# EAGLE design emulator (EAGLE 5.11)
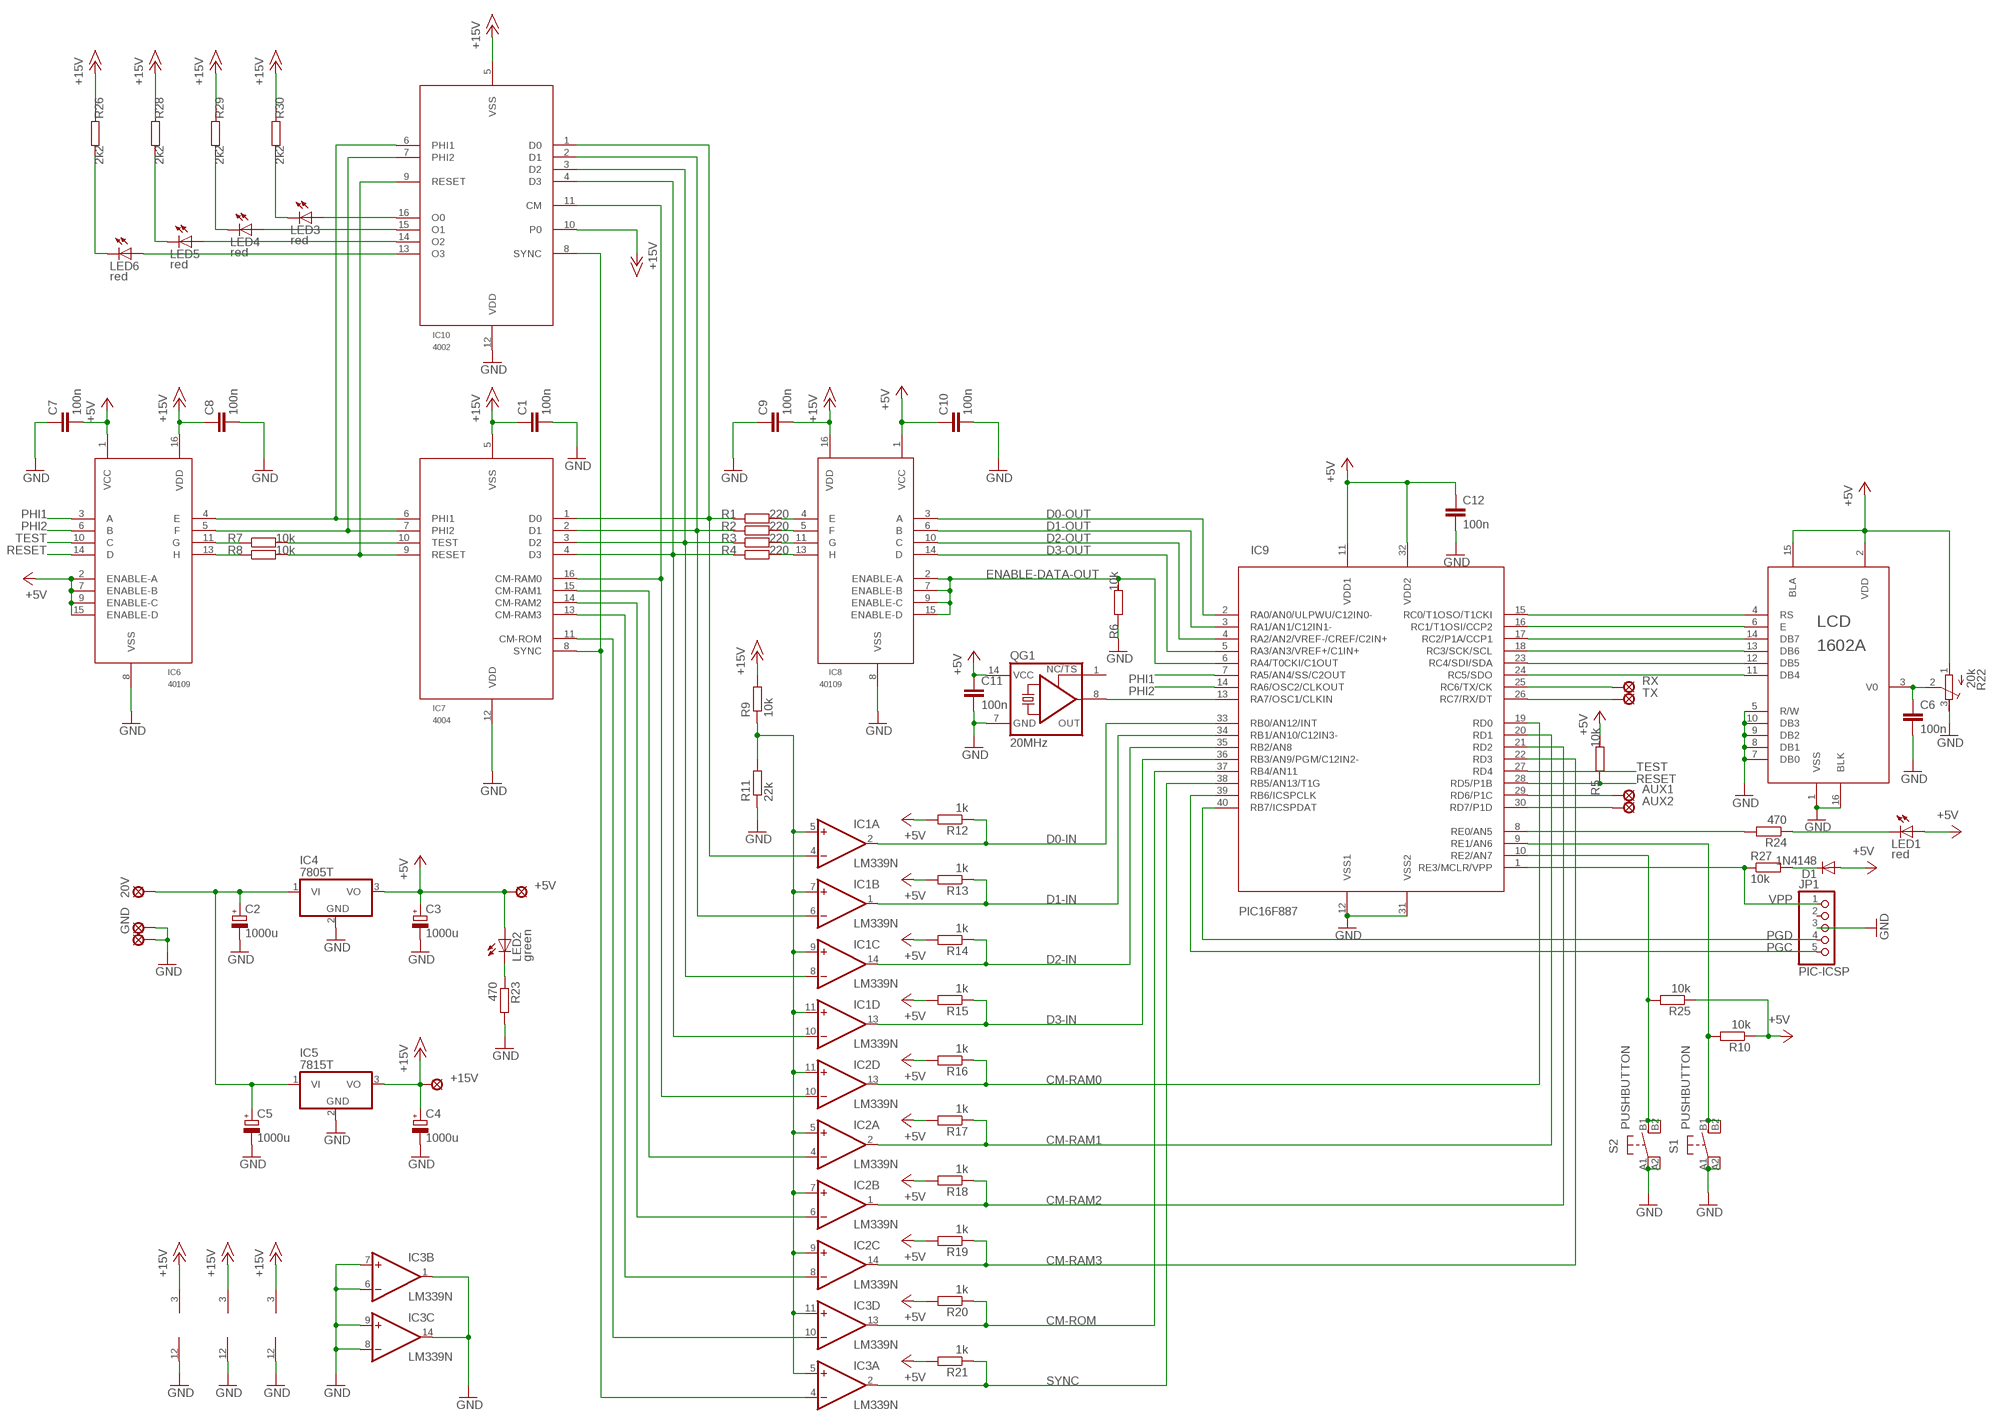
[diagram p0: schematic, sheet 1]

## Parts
20V  LSP10  [LSP10]
+5V  LSP10  [LSP10]
+15V  LSP10  [LSP10]
AUX1  LSP10  [LSP10]
AUX2  LSP10  [LSP10]
C1  100n  C-EU050-050X075  [C050-050X075]
C2  1000u  CPOL-EUE7.5-16  [E7,5-16]
C3  1000u  CPOL-EUE7.5-16  [E7,5-16]
C4  1000u  CPOL-EUE7.5-16  [E7,5-16]
C5  1000u  CPOL-EUE7.5-16  [E7,5-16]
C6  100n  C-EU050-050X075  [C050-050X075]
C7  100n  C-EU050-050X075  [C050-050X075]
C8  100n  C-EU050-050X075  [C050-050X075]
C9  100n  C-EU050-050X075  [C050-050X075]
C10  100n  C-EU050-050X075  [C050-050X075]
C11  100n  C-EU050-055X075  [C050-055X075]
C12  100n  C-EU050-050X075  [C050-050X075]
D1  1N4148  1N4148DO35-7  [DO35-7]
GND  LSP10  [LSP10]
GND29  LSP10  [LSP10]
IC1  LM339N  [DIL14]
IC2  LM339N  [DIL14]
IC3  LM339N  [DIL14]
IC4  7805T  [TO220H]
IC5  7815T  [TO220H]
IC6  40109  [DIL16]
IC7  4004  [DIL16/DIL40]
IC8  40109  [DIL16]
IC9  PIC16F887  [DIL40]
IC10  4002  [DIL16]
JP1  PIC-ICSP  PINHD-1X5  [1X05]
LCD  1602A  [1602A]
LED1  red  LED5MM  [LED5MM]
LED2  green  LED5MM  [LED5MM]
LED3  red  LED5MM  [LED5MM]
LED4  red  LED5MM  [LED5MM]
LED5  red  LED5MM  [LED5MM]
LED6  red  LED5MM  [LED5MM]
QG1  20MHz  XO-14  [DIL14S]
R1  220  R-EU_0309/10  [0309/10]
R2  220  R-EU_0309/10  [0309/10]
R3  220  R-EU_0309/10  [0309/10]
R4  220  R-EU_0309/10  [0309/10]
R5  10k  R-EU_0309/10  [0309/10]
R6  10k  R-EU_0309/10  [0309/10]
R7  10k  R-EU_0309/10  [0309/10]
R8  10k  R-EU_0309/10  [0309/10]
R9  10k  R-EU_0309/10  [0309/10]
R10  10k  R-EU_0309/10  [0309/10]
R11  22k  R-EU_0309/10  [0309/10]
R12  1k  R-EU_0309/10  [0309/10]
R13  1k  R-EU_0309/10  [0309/10]
R14  1k  R-EU_0309/10  [0309/10]
R15  1k  R-EU_0309/10  [0309/10]
R16  1k  R-EU_0309/10  [0309/10]
R17  1k  R-EU_0309/10  [0309/10]
R18  1k  R-EU_0309/10  [0309/10]
R19  1k  R-EU_0309/10  [0309/10]
R20  1k  R-EU_0309/10  [0309/10]
R21  1k  R-EU_0309/10  [0309/10]
R22  20k  R-TRIMM3339P  [RTRIM3339P]
R23  470  R-EU_0309/10  [0309/10]
R24  470  R-EU_0309/10  [0309/10]
R25  10k  R-EU_0309/10  [0309/10]
R26  2k2  R-EU_0309/10  [0309/10]
R27  10k  R-EU_0309/10  [0309/10]
R28  2k2  R-EU_0309/10  [0309/10]
R29  2k2  R-EU_0309/10  [0309/10]
R30  2k2  R-EU_0309/10  [0309/10]
RX  LSP10  [LSP10]
S1  PUSHBUTTON  [PUSHBUTTON]
S2  PUSHBUTTON  [PUSHBUTTON]
TX  LSP10  [LSP10]

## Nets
+5V: +5V.MP C3.+ C7.2 C10.1 C11.1 C12.1 D1.A IC4.3(VO) IC6.1(VCC) IC6.2(ENABLE-A) IC6.7(ENABLE-B) IC6.9(ENABLE-C) IC6.15(ENABLE-D) IC8.1(VCC) IC9.11(VDD1) IC9.32(VDD2) LCD.2(VDD) LCD.15(BLA) LED1.A LED2.A QG1.14(VCC) R5.2 R10.1 R12.2 R13.2 R14.2 R15.2 R16.2 R17.2 R18.2 R19.2 R20.2 R21.2 R22.1(E) R25.1
+15V: +15V.MP C1.1 C4.+ C8.1 C9.2 IC1.3(P:V+) IC2.3(P:V+) IC3.3(P:V+) IC5.3(VO) IC6.16(VDD) IC7.5(VSS) IC8.16(VDD) IC10.5(VSS) IC10.10(P0) R9.2 R26.1 R28.1 R29.1 R30.1
CM-RAM0: IC2.13(D:OUT) IC9.19(RD0) R16.1
CM-RAM1: IC2.2(A:OUT) IC9.20(RD1) R17.1
CM-RAM2: IC2.1(B:OUT) IC9.21(RD2) R18.1
CM-RAM3: IC2.14(C:OUT) IC9.22(RD3) R19.1
CM-ROM: IC3.13(D:OUT) IC9.37(RB4/AN11) R20.1
D0-IN: IC1.2(A:OUT) IC9.33(RB0/AN12/INT) R12.1
D0-OUT: IC8.3(A) IC9.2(RA0/AN0/ULPWU/C12IN0-)
D1-IN: IC1.1(B:OUT) IC9.34(RB1/AN10/C12IN3-) R13.1
D1-OUT: IC8.6(B) IC9.3(RA1/AN1/C12IN1-)
D2-IN: IC1.14(C:OUT) IC9.35(RB2/AN8) R14.1
D2-OUT: IC8.10(C) IC9.4(RA2/AN2/VREF-/CREF/C2IN+)
D3-IN: IC1.13(D:OUT) IC9.36(RB3/AN9/PGM/C12IN2-) R15.1
D3-OUT: IC8.14(D) IC9.5(RA3/AN3/VREF+/C1IN+)
ENABLE-DATA-OUT: IC8.2(ENABLE-A) IC8.7(ENABLE-B) IC8.9(ENABLE-C) IC8.15(ENABLE-D) IC9.6(RA4/T0CKI/C1OUT) R6.2
GND: C1.2 C2.- C3.- C4.- C5.- C6.2 C7.1 C8.2 C9.1 C10.2 C11.2 C12.2 GND29.MP GND.MP IC1.12(P:GND) IC2.12(P:GND) IC3.1(B:OUT) IC3.6(B:-IN) IC3.7(B:+IN) IC3.8(C:-IN) IC3.9(C:+IN) IC3.12(P:GND) IC3.14(C:OUT) IC4.2(GND) IC5.2(GND) IC6.8(VSS) IC7.12(VDD) IC8.8(VSS) IC9.12(VSS1) IC9.31(VSS2) IC10.12(VDD) JP1.3 LCD.1(VSS) LCD.5(R/W) LCD.7(DB0) LCD.8(DB1) LCD.9(DB2) LCD.10(DB3) LCD.16(BLK) QG1.7(GND) R6.1 R11.1 R22.3(A) R23.2 S1.A1(P) S1.A2(P1) S2.A1(P) S2.A2(P1)
LCD-DB4: IC9.24(RC5/SDO) LCD.11(DB4)
LCD-DB5: IC9.23(RC4/SDI/SDA) LCD.12(DB5)
LCD-DB6: IC9.18(RC3/SCK/SCL) LCD.13(DB6)
LCD-DB7: IC9.17(RC2/P1A/CCP1) LCD.14(DB7)
LCD-E: IC9.16(RC1/T1OSI/CCP2) LCD.6(E)
LCD-RS: IC9.15(RC0/T1OSO/T1CKI) LCD.4(RS)
N$1: IC1.4(A:-IN) IC7.1(D0) IC10.1(D0) R1.1
N$2: IC1.6(B:-IN) IC7.2(D1) IC10.2(D1) R2.1
N$3: IC1.8(C:-IN) IC7.3(D2) IC10.3(D2) R3.1
N$4: IC1.10(D:-IN) IC7.4(D3) IC10.4(D3) R4.1
N$5: IC8.4(E) R1.2
N$6: IC8.5(F) R2.2
N$7: IC8.11(G) R3.2
N$8: IC8.13(H) R4.2
N$9: IC6.4(E) IC7.6(PHI1) IC10.6(PHI1)
N$10: IC6.5(F) IC7.7(PHI2) IC10.7(PHI2)
N$11: IC6.11(G) R7.1
N$12: IC6.13(H) R8.1
N$15: IC7.10(TEST) R7.2
N$16: IC7.9(RESET) IC10.9(RESET) R8.2
N$17: IC1.5(A:+IN) IC1.7(B:+IN) IC1.9(C:+IN) IC1.11(D:+IN) IC2.5(A:+IN) IC2.7(B:+IN) IC2.9(C:+IN) IC2.11(D:+IN) IC3.5(A:+IN) IC3.11(D:+IN) R9.1 R11.2
N$19: IC2.10(D:-IN) IC7.16(CM-RAM0) IC10.11(CM)
N$20: IC2.4(A:-IN) IC7.15(CM-RAM1)
N$21: IC2.6(B:-IN) IC7.14(CM-RAM2)
N$22: IC2.8(C:-IN) IC7.13(CM-RAM3)
N$23: IC3.10(D:-IN) IC7.11(CM-ROM)
N$24: IC3.4(A:-IN) IC7.8(SYNC) IC10.8(SYNC)
N$25: C6.1 LCD.3(V0) R22.2(S)
N$26: IC9.13(RA7/OSC1/CLKIN) QG1.8(OUT)
N$27: LED1.K(C) R24.1
N$28: 20V.MP C2.+ C5.+ IC4.1(VI) IC5.1(VI)
N$29: AUX1.MP IC9.29(RD6/P1C)
N$30: AUX2.MP IC9.30(RD7/P1D)
N$31: D1.C R27.2
N$32: IC9.9(RE1/AN6) R10.2 S1.B1(S) S1.B2(S1)
N$33: IC9.10(RE2/AN7) R25.2 S2.B1(S) S2.B2(S1)
N$34: LED2.K(C) R23.1
N$40: IC9.25(RC6/TX/CK) RX.MP
N$41: IC9.26(RC7/RX/DT) TX.MP
N$42: IC9.8(RE0/AN5) R24.2
N$47: IC10.16(O0) LED3.A
N$48: IC10.15(O1) LED4.A
N$49: IC10.14(O2) LED5.A
N$50: IC10.13(O3) LED6.A
N$51: LED3.K(C) R30.2
N$52: LED4.K(C) R29.2
N$53: LED5.K(C) R28.2
N$54: LED6.K(C) R26.2
PGC: IC9.39(RB6/ICSPCLK) JP1.5
PGD: IC9.40(RB7/ICSPDAT) JP1.4
PHI1: IC6.3(A) IC9.7(RA5/AN4/SS/C2OUT)
PHI2: IC6.6(B) IC9.14(RA6/OSC2/CLKOUT)
RESET: IC6.14(D) IC9.28(RD5/P1B) R5.1
SYNC: IC3.2(A:OUT) IC9.38(RB5/AN13/T1G) R21.1
TEST: IC6.10(C) IC9.27(RD4)
VPP: IC9.1(RE3/MCLR/VPP) JP1.1 R27.1
Unconnected: JP1.2 QG1.1(TS)

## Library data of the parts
20V +5V +15V AUX1 AUX2 GND GND29 RX TX = solpad:LSP10: SOLDER PAD
C1 C6-C12 = rcl:C-EU: CAPACITOR, European symbol
C2-C5 = rcl:CPOL-EU: POLARIZED CAPACITOR, European symbol
D1 = diode:1N4148: DIODE
IC1-IC3 = linear:LM339: Low Power Low Offset Voltage Quad Comparators with open collector; LM139/LM239/LM339/LM2901/LM3302
IC4 IC5 = linear:78*: Positive VOLTAGE REGULATOR Source: http://cache.national.com/ds/LM/LM78L05.pdf http://www.fairchildsemi.com/ds/LM/LM7805.pdf
IC6 IC8 = 4004:40109
IC7 = 4004:4004
IC9 = pic16f887:PIC16F887
IC10 = 4004:4002
JP1 = pinhead:PINHD-1X5: PIN HEADER
LCD = 1602A:1602A
LED1-LED6 = led:LED: LED
QG1 = crystal:XO-: CRYSTAL; OC_FARNELL: unknown; OC_NEWARK: unknown
R1-R21 R23-R30 = rcl:R-EU_: RESISTOR, European symbol
R22 = rcl:R-TRIMM: Trimm resistor
S1 S2 = cartridge:PUSHBUTTON

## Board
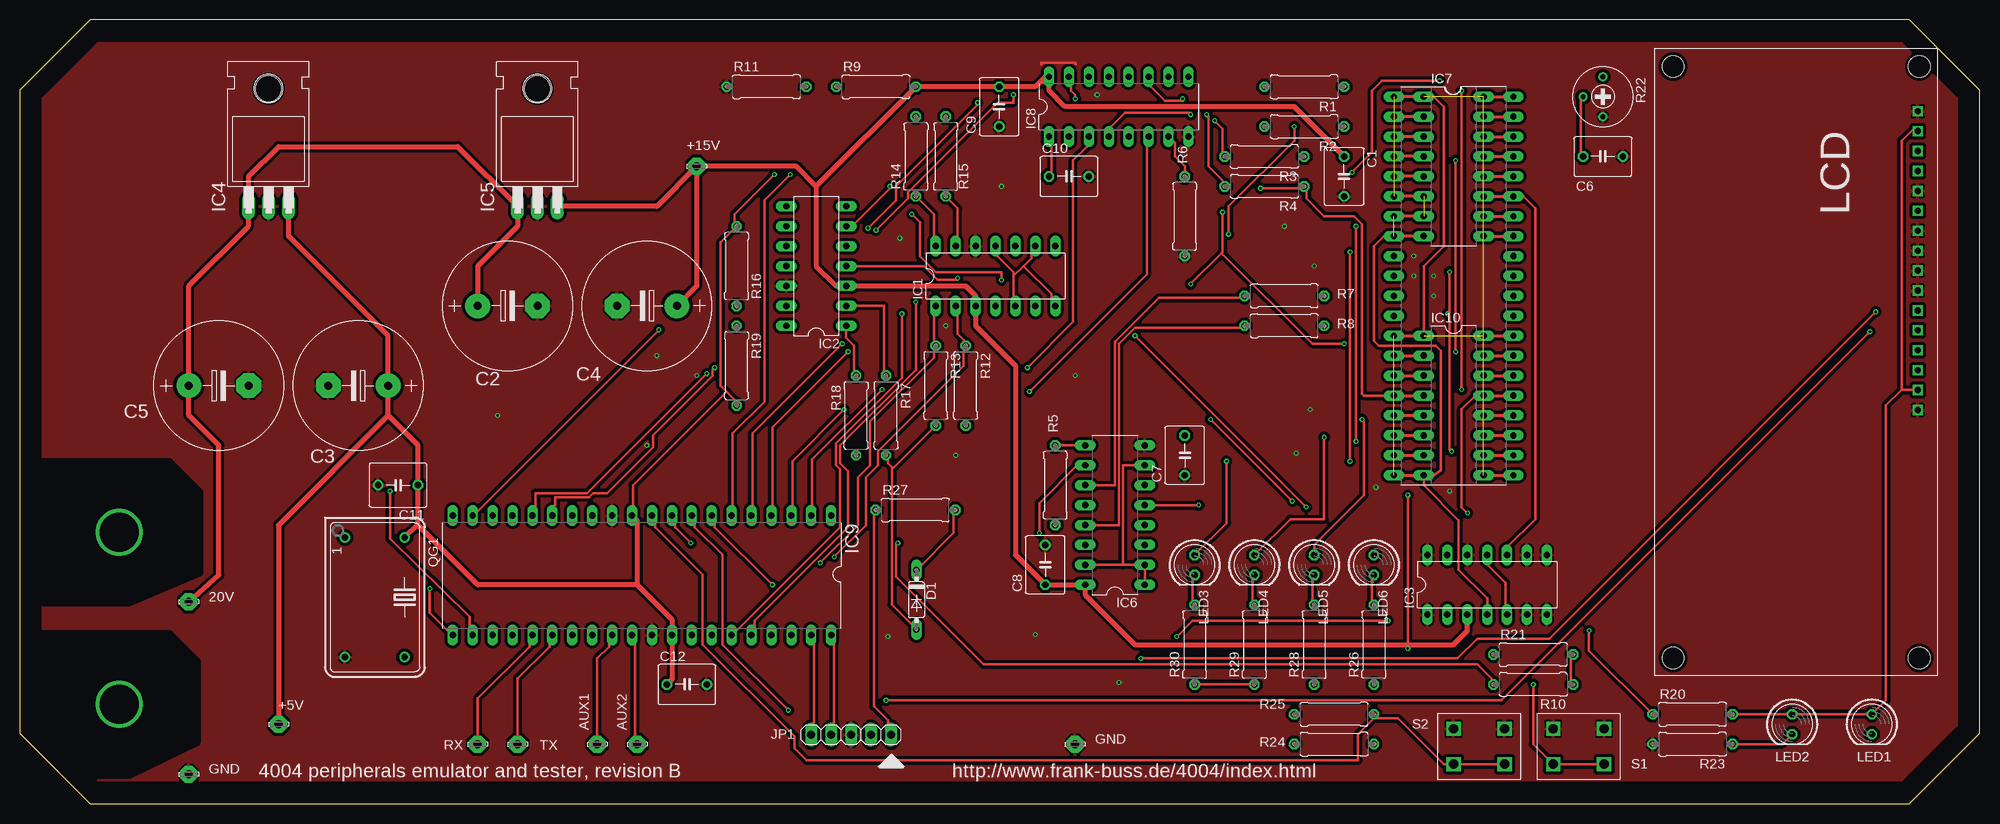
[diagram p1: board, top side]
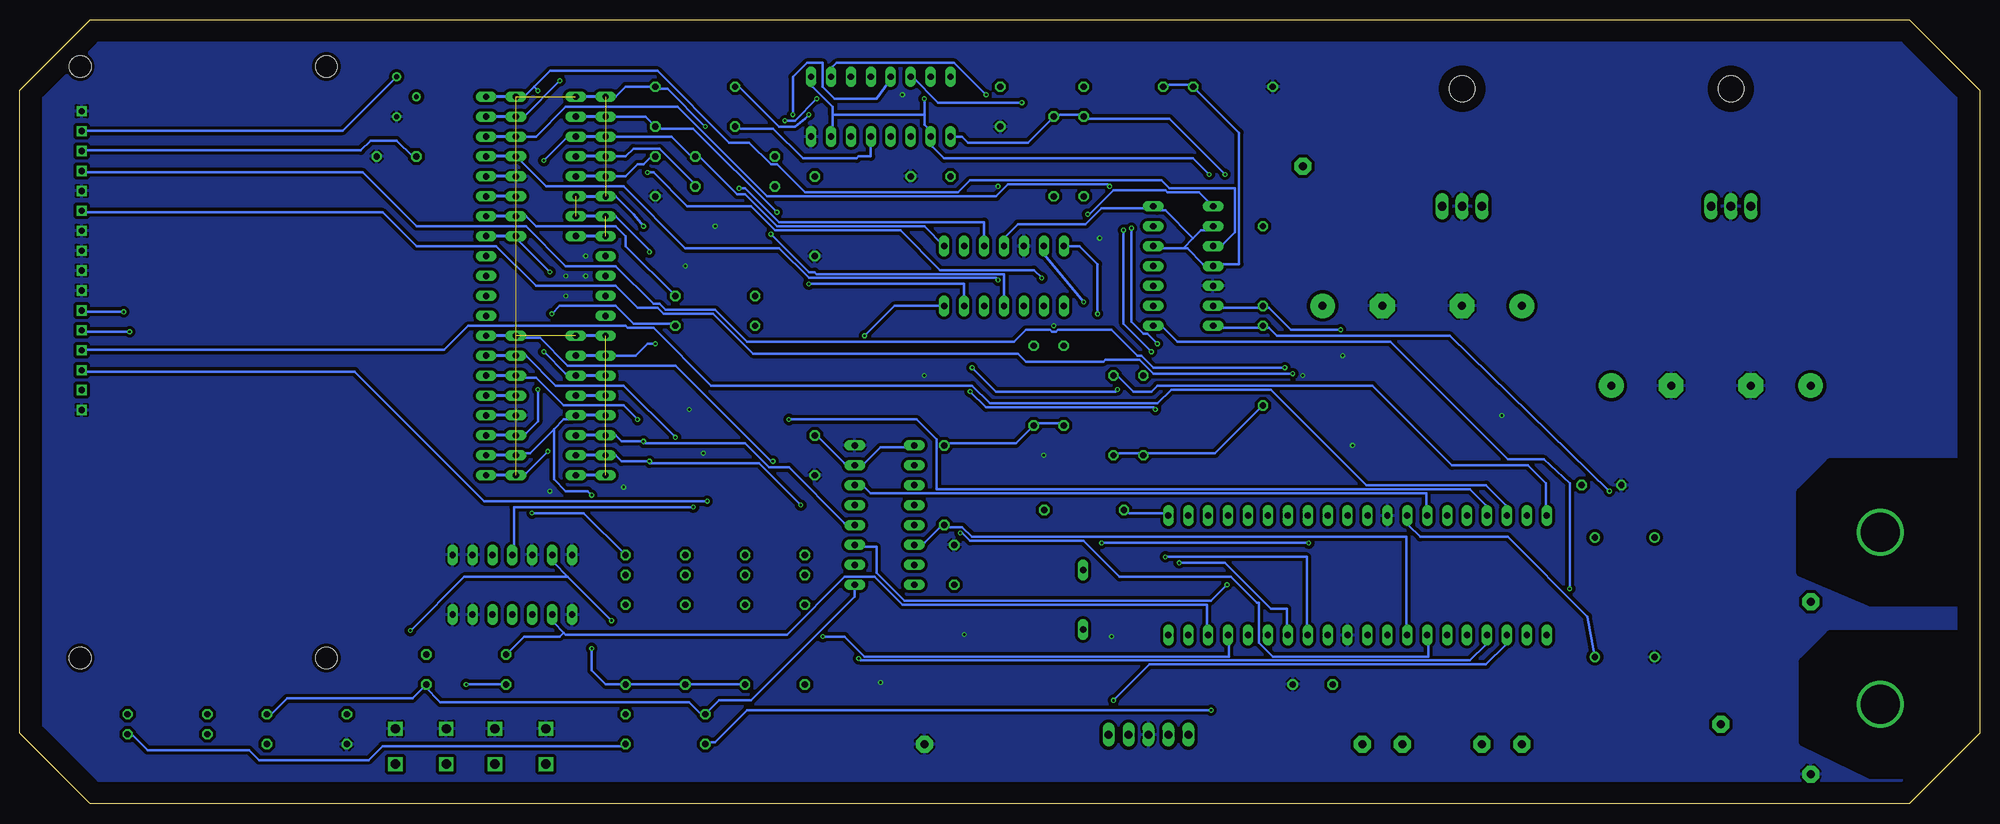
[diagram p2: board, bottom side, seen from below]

Size 250 x 100 mm. Coordinates in mm from the lower left corner, seen from the top.
Outline: 9,0 241,0 250,9 250,91 241,100 9,100 0,91 0,9 9,0
Copper layers (1*16): Top 0.035mm / dielectric 1.5mm / Bottom 0.035mm
Design rules "ITead_rule *": minimum track width 12mil, minimum drill 12mil, track to track 8mil, track to pad 8mil, pad to pad 8mil, via to via 8mil, smd to smd 0mil, copper to edge 10mil, drill to drill 10mil, minimum pad ring 10mil, minimum via ring 6mil, stop-mask expansion 2mil, vias tented up to drill 100mil, thermal gap 10mil
tRestrict: area 2.5,3.8 to 22.5,21.6; area 2.5,25.8 to 22.9,43.5
bRestrict: area 2.5,3.8 to 22.5,21.6; area 2.5,25.8 to 22.9,43.5

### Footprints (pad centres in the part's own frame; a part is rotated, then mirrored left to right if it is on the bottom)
LSP10 = drill 1.016 pad 2.159 octagon: MP 0,0
C050-050X075 = drill 0.813 octagon: 1 -2.54,0; 2 2.54,0
E7,5-16 = drill 1.016 pad 3.15 round: + -3.81,0 | drill 1.016 pad 3.15 octagon: - 3.81,0
C050-055X075 = drill 0.813 octagon: 1 -2.54,0; 2 2.54,0
DO35-7 = drill 0.813 long: A 3.81,0; C -3.81,0
DIL14 = drill 0.813 long: 1 -7.62,-3.81; 2 -5.08,-3.81; 3 -2.54,-3.81; 4 0,-3.81; 5 2.54,-3.81; 6 5.08,-3.81; 7 7.62,-3.81; 8 7.62,3.81; 9 5.08,3.81; 10 2.54,3.81; 11 0,3.81; 12 -2.54,3.81; 13 -5.08,3.81; 14 -7.62,3.81
TO220H = drill 1.118 long: 1 -2.54,-10.16; 2 0,-10.16; 3 2.54,-10.16 | hole 3.302: 0,4.826
DIL16 = drill 0.813 long: 1 -7.62,-3.81; 2 -5.08,-3.81; 3 -2.54,-3.81; 4 0,-3.81; 5 2.54,-3.81; 6 5.08,-3.81; 7 7.62,-3.81; 8 10.16,-3.81; 9 10.16,3.81; 10 7.62,3.81; 11 5.08,3.81; 12 2.54,3.81; 13 0,3.81; 14 -2.54,3.81; 15 -5.08,3.81; 16 -7.62,3.81
DIL16/DIL40 = drill 0.813 long: 1 -8.89,-3.81; 2 -6.35,-3.81; 3 -3.81,-3.81; 4 -1.27,-3.81; 5 1.27,-3.81; 6 3.81,-3.81; 7 6.35,-3.81; 8 8.89,-3.81; 9 8.89,3.81; 10 6.35,3.81; 11 3.81,3.81; 12 1.27,3.81; 13 -1.27,3.81; 14 -3.81,3.81; 15 -6.35,3.81; 16 -8.89,3.81; 17 -8.89,-7.62; 18 -6.35,-7.62; 19 6.35,-7.62; 20 8.89,-7.62; 21 -3.81,-7.62; 22 -1.27,-7.62; 23 3.81,-7.62; 24 1.27,-7.62; 25 11.43,-7.62; 26 13.97,-7.62; 27 16.51,-7.62; 28 19.05,-7.62; 29 21.59,-7.62; 30 24.13,-7.62; 31 26.67,-7.62; 32 29.21,-7.62; 33 31.75,-7.62; 34 34.29,-7.62; 35 36.83,-7.62; 36 39.37,-7.62; 37 39.37,7.62; 38 36.83,7.62; 39 34.29,7.62; 40 31.75,7.62; 41 29.21,7.62; 42 26.67,7.62; 43 24.13,7.62; 44 21.59,7.62; 45 19.05,7.62; 46 16.51,7.62; 47 13.97,7.62; 48 11.43,7.62; 49 8.89,7.62; 50 6.35,7.62; 51 3.81,7.62; 52 1.27,7.62; 53 -1.27,7.62; 54 -3.81,7.62; 55 -6.35,7.62; 56 -8.89,7.62
DIL40 = drill 0.813 long: 1 -24.13,-7.62; 2 -21.59,-7.62; 3 -19.05,-7.62; 4 -16.51,-7.62; 5 -13.97,-7.62; 6 -11.43,-7.62; 7 -8.89,-7.62; 8 -6.35,-7.62; 9 -3.81,-7.62; 10 -1.27,-7.62; 11 1.27,-7.62; 12 3.81,-7.62; 13 6.35,-7.62; 14 8.89,-7.62; 15 11.43,-7.62; 16 13.97,-7.62; 17 16.51,-7.62; 18 19.05,-7.62; 19 21.59,-7.62; 20 24.13,-7.62; 21 24.13,7.62; 22 21.59,7.62; 23 19.05,7.62; 24 16.51,7.62; 25 13.97,7.62; 26 11.43,7.62; 27 8.89,7.62; 28 6.35,7.62; 29 3.81,7.62; 30 1.27,7.62; 31 -1.27,7.62; 32 -3.81,7.62; 33 -6.35,7.62; 34 -8.89,7.62; 35 -11.43,7.62; 36 -13.97,7.62; 37 -16.51,7.62; 38 -19.05,7.62; 39 -21.59,7.62; 40 -24.13,7.62
1X05 = drill 1.016 long: 1 -5.08,0; 2 -2.54,0; 3 0,0; 4 2.54,0; 5 5.08,0
1602A = drill 0.8 square: 1 -31.15,14.29; 2 -28.61,14.29; 3 -26.07,14.29; 4 -23.53,14.29; 5 -20.99,14.29; 6 -18.45,14.29; 7 -15.91,14.29; 8 -13.37,14.29; 9 -10.83,14.29; 10 -8.29,14.29; 11 -5.75,14.29; 12 -3.21,14.29; 13 -0.67,14.29; 14 1.87,14.29; 15 4.41,14.29; 16 6.95,14.29 | hole 2.8: -36.85,14.49; 38.55,14.49; 38.55,-16.91; -36.85,-16.91
LED5MM = drill 0.813 octagon: A -1.27,0; K 1.27,0
DIL14S = drill 0.813 round: 1 -7.62,-3.81; 7 7.62,-3.81; 8 7.62,3.81; 14 -7.62,3.81
0309/10 = drill 0.813 octagon: 1 -5.08,0; 2 5.08,0
RTRIM3339P = drill 0.61 round: 1 -2.54,0; 2 0,-2.54; 3 2.54,0
PUSHBUTTON = drill 1.2 square: A1 0,4.5; A2 6.5,4.5; B1 0,0; B2 6.5,0

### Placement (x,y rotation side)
20V  21.59,25.75 0 top
+5V  33.02,10.16 0 top
+15V  86.36,81.28 0 top
AUX1  73.66,7.62 0 top
AUX2  78.74,7.62 0 top
C1  168.91,80.01 270 top
C2  62.23,63.5 0 top
C3  43.18,53.34 180 top
C4  80.01,63.5 180 top
C5  25.4,53.34 0 top
C6  201.93,82.55 0 top
C7  148.59,44.45 90 top
C8  130.81,30.48 90 top
C9  124.93,88.9 90 top
C10  133.82,80.01 0 top
C11  48.26,40.64 180 top
C12  85.09,15.24 0 top
D1  114.36,26.03 270 top
GND  21.59,3.81 0 top
GND29  134.62,7.62 0 top
IC1  124.46,67.31 0 top
IC2  101.6,68.58 90 top
IC3  187.16,27.94 0 top
IC4  31.75,86.36 0 top
IC5  66.04,86.36 0 top
IC6  139.7,35.56 90 top
IC7  182.88,81.28 270 top
IC8  138.9,88.9 0 top
IC9  79.37,29.15 180 top
IC10  182.88,52.07 270 top
JP1  106.04,8.83 180 top
LCD  227.78,57.17 270 top
LED1  236.22,10.16 270 top
LED2  226.06,10.16 270 top
LED3  149.86,30.48 270 top
LED4  157.48,30.48 270 top
LED5  165.1,30.48 270 top
LED6  172.72,30.48 270 top
QG1  45.3,26.35 270 top
R1  163.83,91.44 180 top
R2  163.83,86.36 180 top
R3  158.75,82.55 180 top
R4  158.75,78.74 180 top
R5  132.08,40.64 90 top
R6  148.59,74.93 90 top
R7  161.29,64.77 0 top
R8  161.29,60.96 0 top
R9  109.22,91.44 0 top
R10  193.04,15.24 180 top
R11  95.25,91.44 0 top
R12  120.65,53.34 270 top
R13  116.84,53.34 270 top
R14  114.3,82.55 90 top
R15  118.11,82.55 90 top
R16  91.44,68.58 90 top
R17  110.49,49.53 270 top
R18  106.68,49.53 270 top
R19  91.44,55.88 270 top
R20  213.36,11.43 0 top
R21  193.04,19.05 0 top
R22  201.93,90.17 270 top
R23  213.36,7.62 180 top
R24  167.64,7.62 180 top
R25  167.64,11.43 0 top
R26  172.72,20.32 90 top
R27  114.24,37.47 0 top
R28  165.1,20.32 90 top
R29  157.48,20.32 90 top
R30  149.86,20.32 90 top
RX  58.42,7.62 0 top
S1  195.58,5.08 0 top
S2  182.88,5.08 0 top
TX  63.5,7.62 0 top

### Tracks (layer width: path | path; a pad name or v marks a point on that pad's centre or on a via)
+5V  (via drill 0.3)
  Top 0.305: C10.1 131.32,80.01 131.57,80.26 131.57,84.84 131.32,85.09 IC8.1 | 140.72,30.48 IC6.15 | 140.72,30.48 IC6.2 IC6.1 | 111.25,42.67 111.25,42.93 110.74,43.43 110.74,43.69 110.49,43.94 R17.2 | 111.25,42.67 111.25,25.4 114.3,22.35 D1.A | 91.19,73.41 89.41,71.63 89.41,53.34 90.17,52.58 | 90.17,52.58 91.44,51.31 R19.2 | R13.2 111.25,42.67 | v96.27,80.26 91.19,75.18 91.19,73.41 | 91.19,73.41 R16.2 | 90.17,52.58 78.23,40.64 78.23,36.83 IC9.11 | 240.03,52.83 242.06,52.83 LCD.15 | 240.03,52.83 240.03,84.58 241.55,86.11 242.06,86.11 242.06,85.85 LCD.2 | 240.03,52.83 238,50.8 238,13.21 LED1.A LED2.A R20.2 | IC6.9 R5.2 | R10.1 197.87,15.49 197.87,18.29 198.12,18.54 R21.2 | IC6.7 140.72,43.18 140.72,30.48
  Top 0.61: C12.1 83.18,15.87 IC9.32 83.18,23.5 78.74,27.94 | IC4.3 34.29,72.39 46.99,59.69 C3.+ 46.99,49.53 | 46.99,49.53 50.8,45.72 C11.1 50.8,35.66 50.75,35.61 | +5V.MP 33.02,35.56 46.99,49.53 | 50.75,35.61 QG1.14 | 78.74,27.94 58.42,27.94 50.75,35.61 | 78.74,27.94 78.74,36.13 IC9.11
  Bottom 0.305: IC8.1 129.79,85.09 129.03,84.33 121.41,84.33 R15.2 117.6,87.63 117.35,87.88 114.55,87.88 R14.2 114.05,87.38 103.38,87.38 v96.27,80.26 | 106.93,44.7 109.73,44.7 109.98,44.45 R17.2 | R19.2 97.54,44.7 106.93,44.7 | 106.93,44.7 R18.2 | R22.1 208.79,85.85 242.06,85.85 LCD.2 | C7.2 148.34,46.99 144.78,43.43 143.76,43.43 IC6.7 143.26,43.43 142.24,43.43 140.21,45.47 136.14,45.47 IC6.9 | R13.2 117.09,48.51 120.4,48.51 R12.2 122.94,45.97 131.32,45.97 131.57,45.72 R5.2 | 198.37,14.99 199.9,13.46 215.9,13.46 217.93,11.43 R20.2 | IC6.1 143.51,26.42 156.72,13.21 160.78,13.21 R25.1 163.07,11.43 164.59,12.95 196.34,12.95 198.37,14.99 | 198.37,14.99 R10.1
+15V  (via drill 0.3)
  Top 0.305: 177.04,20.32 v177.04,39.37 | R29.1 R30.1
  Top 0.61: C4.+ 86.36,66.04 +15V.MP | 101.6,78.74 101.6,68.58 104.14,66.04 IC2.3 120.65,66.04 121.92,64.77 IC1.3 121.92,60.96 127,55.88 127,31.75 C8.1 IC6.16 135.89,26.67 142.24,20.32 177.04,20.32 | 101.6,78.74 99.06,81.28 +15V.MP | 184.62,24.6 IC3.3 184.62,22.06 182.88,20.32 177.04,20.32 | 101.6,78.74 R9.2 C9.2 129.54,91.44 130.81,92.71 IC8.16 131.28,90.97 133.35,88.9 162.56,88.9 C1.1 | 177.04,20.32 v177.04,19.81 | IC5.3 81.28,76.2 +15V.MP
  Bottom 0.305: C1.1 169.42,82.55 170.43,81.53 171.2,81.53 172.72,80.01 IC7.5 | IC10.5 179.58,49.02 180.59,49.02 181.86,47.75 | 181.86,47.75 184.91,44.7 186.44,44.7 IC10.10 | v177.04,39.37 177.55,39.88 180.34,39.88 181.86,41.4 181.86,47.75 | v177.04,19.81 177.04,17.02 175.26,15.24 R26.1 R28.1 R29.1
CM-RAM0  (via drill 0.3)
  Top 0.305: v81.53,60.45 57.91,36.83 IC9.19
  Bottom 0.305: v81.53,60.45 87.88,60.45 90.68,63.25 | 90.68,63.25 90.93,63.5 R16.1 | IC2.13 97.54,63.25 90.68,63.25
CM-RAM1
  Top 0.305: IC2.2 110.24,63.5 110.24,54.86 R17.1
  Bottom 0.305: R17.1 109.98,54.61 107.95,52.58 105.66,52.58 104.9,53.34 77.47,53.34 67.31,43.18 57.66,43.18 55.37,40.89 55.37,36.83 IC9.20
CM-RAM2  (via drill 0.3)
  Top 0.305: v52.32,27.43 52.32,24.38 55.12,21.59 IC9.21 | R18.1 106.43,54.86 106.43,58.42 105.41,59.44 IC2.1
  Bottom 0.305: v52.32,27.43 52.32,40.89 55.63,43.94 60.2,43.94 75.18,58.93 102.36,58.93 104.39,60.96 IC2.1
CM-RAM3  (via drill 0.3)
  Top 0.305: v47.24,39.88 47.24,33.78 57.4,23.88 57.4,21.84 57.66,21.59 IC9.22
  Bottom 0.305: v47.24,39.88 67.56,59.69 89.66,59.69 90.68,60.71 | 90.68,60.71 90.93,60.96 R19.1 | IC2.14 97.54,60.71 90.68,60.71
CM-ROM  (via drill 0.3)
  Top 0.305: v147.57,21.34 149.61,23.37 v174.5,23.37 | R20.1 200.15,19.56 v200.15,22.1
  Bottom 0.305: v147.57,21.34 144.78,21.34 142.24,18.8 95.76,18.8 95.76,21.34 IC9.37 | 180.09,28.96 181.86,30.73 181.86,31.75 IC3.13 | v174.5,23.37 180.09,28.96 | v200.15,22.1 193.29,28.96 180.09,28.96
D0-IN  (via drill 0.3)
  Top 0.305: v103.89,31.5 107.95,35.56 107.95,41.66 109.47,43.18 109.47,44.96 120.4,55.88 120.4,57.66 120.65,57.91 R12.1 120.65,58.93 119.63,59.94 119.63,63.25 IC1.2
  Bottom 0.305: v103.89,31.5 85.85,31.5 85.85,21.59 IC9.33
D0-OUT  (via drill 0.3)
  Top 0.305: v109.98,52.83 101.09,43.94 101.09,36.83 IC9.2 | v128.52,55.63 134.37,61.47 134.37,82.04 136.14,83.82 136.14,85.09 IC8.3
  Bottom 0.305: v109.98,52.83 110.24,52.58 125.48,52.58 v128.52,55.63
D1-IN  (via drill 0.3)
  Top 0.305: v102.11,30.73 106.93,35.56 106.93,41.66 108.46,43.18 108.46,48.77 116.59,56.9 116.59,57.66 | 116.59,57.66 116.84,57.91 R13.1 | IC1.1 116.59,63.25 116.59,57.66
  Bottom 0.305: v102.11,30.73 96.27,30.73 90.42,24.89 88.39,24.89 88.39,21.59 IC9.34
D1-OUT  (via drill 0.3)
  Top 0.305: v105.16,50.29 98.55,43.69 98.55,36.83 IC9.3 | v128.78,52.58 143.76,67.56 143.76,85.09 IC8.6
  Bottom 0.305: v105.16,50.29 105.41,50.55 126.75,50.55 v128.78,52.58
D2-IN  (via drill 0.3)
  Top 0.305: v112.52,62.48 112.52,54.36 104.14,45.97 104.14,43.18 104.65,42.67 104.65,35.31 90.93,21.59 IC9.35 | R14.1 116.59,75.18 116.59,71.37 IC1.14
  Bottom 0.305: v112.52,62.48 112.52,68.83 114.81,71.12 IC1.14
D2-OUT  (via drill 0.3)
  Top 0.305: v105.66,57.66 96.01,48.01 96.01,36.83 IC9.4 | v109.22,73.15 113.28,77.22 113.28,77.98 124.71,89.41 126.75,89.41 v126.75,90.42
  Bottom 0.305: v105.66,57.66 109.22,61.21 v109.22,73.15 | v126.75,90.42 130.81,94.49 145.8,94.49 146.3,93.98 146.3,92.71 IC8.10
D3-IN  (via drill 0.3)
  Top 0.305: v114.3,64.01 114.3,55.37 104.65,45.72 104.65,43.43 105.66,42.42 105.66,35.31 93.73,23.37 93.73,21.84 93.47,21.59 IC9.36 | R15.1 119.63,75.95 119.63,71.37 IC1.13
  Bottom 0.305: v114.3,64.01 119.38,70.1 IC1.13
D3-OUT  (via drill 0.3)
  Top 0.305: v104.9,58.67 93.47,47.24 93.47,36.83 IC9.5 | v108.2,73.41 111.76,76.96 111.76,78.74 122.17,89.15 v122.17,89.41
  Bottom 0.305: v104.9,58.67 106.17,59.94 106.68,59.94 108.2,61.47 v108.2,73.41 | v122.17,89.41 132.84,89.41 136.14,92.71 IC8.14
ENABLE-DATA-OUT  (via drill 0.3)
  Top 0.305: v98.3,80.26 95,76.96 95,51.31 90.93,47.24 90.93,36.83 IC9.6 | v134.62,89.92 134.62,90.42 134.11,90.93 134.11,92.46 133.86,92.71 IC8.15 | R6.2 148.59,81.28 147.32,82.55 147.32,84.29 IC8.7
  Bottom 0.305: 146.3,87.88 146.3,88.9 148.84,91.44 148.84,92.71 IC8.9 | 146.3,87.88 146.3,85.09 IC8.7 | v98.3,80.26 100.33,82.3 132.08,82.3 133.6,83.82 133.6,85.09 IC8.2 133.86,85.09 133.86,85.85 134.62,86.61 134.62,87.88 | 134.62,87.88 v134.62,89.92 | 134.62,87.88 146.3,87.88
GND  (via drill 0.3)
  Top 0.305: 134.68,94.31 134.62,94.49 130.3,94.49 130.3,94.31
  other vias: 60.96,49.53 81.28,57.15 86.36,54.61 80.01,45.72 134.62,54.61 118.11,60.96 112.27,72.14 125.22,78.74 137.41,90.42 119.38,44.45 129.54,21.59 165.1,68.58 161.29,73.66 182.37,39.88 164.59,50.29 162.81,44.7 172.97,40.39 177.8,69.85 177.8,67.31 180.34,67.31 180.34,64.77 140.21,15.49 110.74,21.34
  pour Bottom (isolate 0.406): 3,90 10,97 240,97 247,90 247,10 240,3 10,3 3,7.46
  pour Top (isolate 0.406): 10,97 240,97 247,90 247,10 240,3 10,3 3,7.46 3,90
LCD-DB4  (via drill 0.3)
  Top 0.305: v236.73,62.74 195.07,21.08 185.93,21.08 183.39,18.54 v143,18.54
  Bottom 0.305: v236.73,62.74 242.06,62.74 LCD.11 | v143,18.54 142.75,18.29 65.02,18.29 62.99,20.32 62.99,21.34 IC9.24
LCD-DB5  (via drill 0.3)
  Top 0.305: v235.97,60.2 188.98,13.21 v110.49,13.21
  Bottom 0.305: v235.97,60.2 242.06,60.2 LCD.12 | v110.49,13.21 105.92,17.78 62.99,17.78 60.45,20.32 60.45,21.34 IC9.23
LCD-DB6
  Bottom 0.305: LCD.13 242.06,57.91 195.83,57.91 192.79,60.96 172.72,60.96 172.47,60.71 169.16,60.71 161.8,53.34 128.52,53.34 126.24,51.05 104.9,51.05 103.12,52.83 90.42,52.83 78.23,40.64 62.99,40.64 60.45,38.1 60.45,36.83 IC9.18
LCD-DB7  (via drill 0.3)
  Top 0.305: v162.31,38.61 v151.89,49.02
  Bottom 0.305: v162.31,38.61 190.75,38.61 207.26,55.12 242.06,55.12 LCD.14 | v151.89,49.02 135.64,49.02 133.1,46.48 133.1,40.13 65.02,40.13 62.99,38.1 62.99,36.83 IC9.17
LCD-E  (via drill 0.3)
  Top 0.305: v87.63,54.86 72.39,39.62 65.79,39.62 65.79,38.1 65.53,37.85 65.53,36.83 IC9.16
  Bottom 0.305: v87.63,54.86 105.41,54.86 107.19,56.64 111.51,56.64 111.76,56.39 121.67,56.39 122.68,57.4 156.46,57.4 161.54,62.48 167.89,62.48 168.66,63.25 171.2,63.25 173.99,66.04 184.15,66.04 189.23,71.12 199.39,71.12 203.71,75.44 242.06,75.44 LCD.6
LCD-RS  (via drill 0.3)
  Top 0.305: v88.65,55.63 88.39,55.37 88.39,54.61 80.77,46.99 80.77,45.47 74.93,39.62 73.15,39.62 72.64,39.12 68.33,39.12 68.33,38.1 68.07,37.85 68.07,36.83 IC9.15
  Bottom 0.305: v88.65,55.63 105.41,55.63 106.93,57.15 107.44,57.15 110.74,60.45 117.6,60.45 117.86,60.2 118.36,60.2 118.62,60.45 121.67,60.45 123.19,58.93 157.23,58.93 161.29,62.99 167.64,62.99 168.4,63.75 169.16,63.75 173.99,68.58 180.34,68.58 185.42,73.66 199.39,73.66 206.25,80.52 242.06,80.52 LCD.4
N$1  (via drill 0.3)
  Top 0.305: v154.18,72.64 154.18,76.2 162.56,84.58 v162.56,86.36 | IC10.1 179.07,68.58 181.61,71.12 181.61,88.9 180.34,90.17 IC7.1
  Bottom 0.305: IC1.4 124.46,67.56 148.34,67.56 148.59,67.82 149.35,67.82 v154.18,72.64 | v162.56,86.36 167.39,91.19 168.66,91.19 R1.1 172.72,91.44 173.99,90.17 IC7.1
N$2  (via drill 0.3)
  Top 0.305: 153.29,70.23 153.42,70.36 v153.42,75.44 | 153.29,70.23 v149.35,66.29 | v168.91,58.67 164.85,58.67 153.29,70.23
  Bottom 0.305: IC1.6 129.54,66.29 v149.35,66.29 | v153.42,75.44 164.08,86.11 168.15,86.11 168.4,86.36 R2.1 170.18,87.63 IC7.2 | v168.91,58.67 169.93,58.67 171.45,57.15 IC10.2
N$3  (via drill 0.3)
  Top 0.305: v183.13,82.04 v183.13,57.66
  Bottom 0.305: IC1.8 134.62,73.66 153.42,73.66 157.48,77.72 158.5,77.72 163.32,82.55 R3.1 164.34,82.55 166.88,85.09 IC7.3 180.09,85.09 v183.13,82.04 | IC10.3 179.32,54.86 180.34,54.86 v183.13,57.66
N$4  (via drill 0.3)
  Top 0.305: 163.83,78.49 v158.24,78.49 | 163.83,78.49 163.83,78.23 164.08,77.98 164.08,77.22 166.37,74.93 170.18,74.93 171.2,73.91 171.2,52.32 171.45,52.07 IC10.4 | R4.1 163.83,78.49
  Bottom 0.305: IC1.10 127,74.17 153.16,74.17 157.48,78.49 v158.24,78.49 | R4.1 163.83,78.99 168.4,83.57 171.7,83.57 172.72,82.55 IC7.4
N$5  (via drill 0.3)
  Top 0.305: v149.35,87.88 149.35,88.14 140.97,88.14 139.19,86.36 139.19,85.34 138.94,85.09 IC8.4
  Bottom 0.305: v149.35,87.88 149.86,87.38 151.13,86.36 153.16,86.36 158.24,91.44 R1.2
N$6
  Bottom 0.305: R2.2 158.24,86.36 157.99,86.11 153.92,86.11 150.11,82.3 143.26,82.3 143,82.55 141.48,82.55 141.48,85.09 IC8.5
N$7  (via drill 0.3)
  Top 0.305: v148.34,89.92 148.34,89.66 146.05,89.66 144.27,91.44 144.27,92.46 144.02,92.71 IC8.11 | v152.4,87.12 153.42,86.11 153.42,82.8 R3.2
  Bottom 0.305: v148.34,89.92 151.13,87.12 v152.4,87.12
N$8  (via drill 0.3)
  Top 0.305: v151.38,87.88 151.64,87.63 151.64,81.28 153.67,79.25 R4.2
  Bottom 0.305: v151.38,87.88 151.38,92.71 149.61,94.49 147.57,94.49 147.57,91.44 146.05,89.92 140.72,89.92 138.68,92.71 IC8.13
N$9  (via drill 0.3)
  Top 0.305: v170.43,73.66 v170.43,46.23
  Bottom 0.305: IC6.4 143.76,35.81 144.78,35.81 151.89,42.93 154.43,42.93 157.48,45.97 170.18,45.97 v170.43,46.23 | v170.43,46.23 170.43,45.97 | v170.43,73.66 171.7,75.18 173.99,77.47 IC7.6 | IC10.6 173.99,46.99 173.23,46.23 v170.43,46.23
N$10  (via drill 0.3)
  Top 0.305: IC6.5 v150.37,38.1 | v169.67,43.69 v169.67,70.36
  Bottom 0.305: v150.37,38.1 155.7,43.43 169.67,43.43 v169.67,43.69 173.23,43.69 173.99,44.45 IC10.7 | v169.67,70.36 169.67,70.61 173.99,74.93 IC7.7
N$11
  Top 0.305: IC6.11 139.7,40.64 139.7,58.93 145.29,64.52 156.21,64.52 R7.1
N$12
  Top 0.305: IC6.13 140.21,35.56 140.21,58.67 142.24,60.71 156.21,60.71 R8.1
N$13  (15 unrouted)
  Top 0.406: 175.26,59.69 179.07,59.69 | 175.26,57.15 179.07,57.15 | 175.26,54.61 179.07,54.61 | 175.26,49.53 179.07,49.53 | 175.26,46.99 179.07,46.99 | 175.26,52.07 179.07,52.07 | 175.26,44.45 179.07,44.45 | 175.26,41.91 179.07,41.91 | 186.69,41.91 190.5,41.91 | 186.69,44.45 190.5,44.45 | 186.69,46.99 190.5,46.99 | 186.69,49.53 190.5,49.53 | 186.69,52.07 190.5,52.07 | 186.69,54.61 190.5,54.61 | 186.69,57.15 190.5,57.15 | 186.69,59.69 190.5,59.69
N$14  (31 unrouted)
  Bottom 0.406: 175.26,90.17 179.07,90.17 | 175.26,87.63 179.07,87.63 | 175.26,85.09 179.07,85.09 | 175.26,82.55 179.07,82.55 | 175.26,80.01 179.07,80.01 | 179.07,77.47 175.26,77.47 | 175.26,74.93 179.07,74.93 | 175.26,72.39 179.07,72.39 | 186.69,72.39 190.5,72.39 | 186.69,74.93 190.5,74.93 | 186.69,77.47 190.5,77.47 | 186.69,80.01 190.5,80.01 | 186.69,82.55 190.5,82.55 | 186.69,85.09 190.5,85.09 | 186.69,87.63 190.5,87.63 | 186.69,90.17 190.5,90.17 | 175.26,59.69 179.07,59.69 | 175.26,57.15 179.07,57.15 | 175.26,54.61 179.07,54.61 | 175.26,52.07 179.07,52.07 | 175.26,49.53 179.07,49.53 | 175.26,46.99 179.07,46.99 | 175.26,44.45 179.07,44.45 | 175.26,41.91 179.07,41.91 | 186.69,41.91 190.5,41.91 | 186.69,44.45 190.5,44.45 | 186.69,46.99 190.5,46.99 | 186.69,49.53 190.5,49.53 | 186.69,52.07 190.5,52.07 | 186.69,54.61 190.5,54.61 | 186.69,57.15 190.5,57.15 | 186.69,59.69 190.5,59.69
N$15
  Bottom 0.305: R7.2 172.72,71.12 172.72,72.39 173.99,73.66 184.15,73.66 185.42,74.93 IC7.10
N$16  (via drill 0.3)
  Top 0.305: v182.63,44.96 182.37,45.21 182.37,62.48 | v182.37,67.82 182.37,62.48 | 182.37,62.48 v182.12,62.48
  Bottom 0.305: IC10.9 186.44,42.16 185.42,42.16 v182.63,44.96 | v182.37,67.82 186.69,72.14 IC7.9 | R8.2 166.62,61.21 171.7,61.21 173.99,63.5 181.1,63.5 v182.12,62.48
N$17  (via drill 0.3)
  Top 0.305: IC1.11 124.71,70.87 124.71,69.85 126.75,67.82 126.75,67.31 | 126.75,67.31 126.75,63.75 IC1.5 | IC1.9 129.03,70.61 129.03,69.6 128.02,68.58 | 126.75,67.31 128.02,68.58 | IC1.7 131.57,64.01 131.57,65.02 128.02,68.58 | IC3.5 189.48,24.13 189.48,28.19 186.94,30.73 186.94,31.75 IC3.11 | v142.24,59.69 v164.08,37.85
  Bottom 0.305: R9.1 103.63,91.44 103.38,91.69 100.58,91.69 R11.2 94.49,85.6 94.49,68.83 98.04,68.83 | 98.04,68.83 99.06,68.83 101.09,70.87 101.6,70.87 | 101.6,70.87 105.16,70.87 IC2.5 | IC2.9 98.3,73.15 99.31,73.15 100.33,72.14 | 101.6,70.87 100.33,72.14 | 100.33,72.14 103.89,75.69 104.9,75.69 IC2.7 105.66,75.95 112.01,75.95 114.05,73.91 122.68,73.91 124.46,72.14 IC1.11 | 98.04,68.83 IC2.11 | v164.08,37.85 186.94,37.85 186.94,31.75 IC3.11 | v142.24,59.69 138.43,63.5 IC1.7
N$18  (via drill 5)
  other vias: 12.7,12.7
N$19  (via drill 0.3)
  Top 0.305: v183.9,90.93 v183.9,52.83
  Bottom 0.305: IC2.10 97.54,71.37 96.52,71.37 95,72.9 95,78.49 103.38,78.49 104.39,79.5 128.78,79.5 130.3,77.98 149.86,77.98 153.42,81.53 154.18,81.53 156.97,84.33 159.51,84.33 168.66,93.47 182.37,93.47 184.4,91.44 | 184.4,91.44 185.67,90.17 IC7.16 | IC10.11 186.44,47.24 185.42,47.24 183.9,48.77 v183.9,52.83 | 184.4,91.44 v183.9,90.93
N$20  (via drill 0.3)
  Top 0.305: IC2.4 115.32,68.58 117.09,66.8 119.63,66.8 v119.63,67.06 | v169.93,80.52 172.47,83.06 172.47,90.93 173.74,92.2 v181.1,92.2
  Bottom 0.305: v119.63,67.06 120.65,68.07 132.59,68.07 137.67,73.15 153.67,73.15 156.72,76.2 164.85,76.2 169.16,80.52 v169.93,80.52 | v181.1,92.2 185.67,87.63 IC7.15
N$21  (via drill 0.3)
  Top 0.305: IC2.6 106.43,73.66 106.43,73.91 111,78.49 v111,78.74
  Bottom 0.305: v111,78.74 111.25,78.99 123.95,78.99 125.48,77.47 154.69,77.47 166.12,88.9 180.34,88.9 184.15,85.09 IC7.14
N$22  (via drill 0.3)
  Top 0.305: v113.79,75.18 114.81,74.17 114.81,69.85 116.84,67.82 125.22,67.82 v125.22,66.8
  Bottom 0.305: IC2.8 99.57,77.98 103.63,77.98 103.89,78.23 110.49,78.23 113.54,75.18 v113.79,75.18 | v125.22,66.8 125.48,67.06 149.35,67.06 153.16,70.87 165.1,70.87 172.97,78.74 182.88,78.74 IC7.13
N$23
  Top 0.305: IC3.10 189.74,31.75 189.74,32.77 193.29,36.32 193.29,75.95 191.77,77.47 IC7.11
N$24
  Top 0.305: IC3.4 187.16,26.2 183.51,29.84 183.51,36.2 179.07,40.64 IC10.8 180.34,41.91 181.23,42.55 181.23,57.78 180.59,58.42 179.07,58.42 175.26,58.42 173.35,58.42 172.72,59.05 172.72,71.12 173.99,72.39 IC7.8
N$25
  Top 0.305: R22.2 199.14,89.92 199.14,82.8 C6.1
  Bottom 0.305: C6.1 199.9,82.55 201.93,84.58 205.23,84.58 206.5,83.31 242.06,83.31 LCD.3
N$26
  Bottom 0.305: QG1.8 50.04,23.88 60.2,34.04 71.37,34.04 72.9,35.56 72.9,36.58 IC9.13
N$27
  Bottom 0.305: R24.1 172.97,7.37 203.71,7.37 205.49,5.59 219.46,5.59 220.73,6.86 233.68,6.86 235.71,8.89 LED1.K
N$28
  Top 0.61: C2.+ 58.42,68.58 63.5,73.66 IC5.1 55.88,83.82 33.02,83.82 29.21,80.01 IC4.1 29.21,73.66 21.59,66.04 C5.+ 21.59,49.53 25.4,45.72 25.4,29.21 20V.MP
N$29
  Top 0.305: AUX1.MP 73.66,18.54 75.18,20.07 75.18,21.08 75.44,21.34 IC9.29
N$30
  Top 0.305: AUX2.MP 78.49,7.87 78.49,21.08 78.23,21.34 IC9.30
N$31
  Top 0.305: D1.C 114.55,29.97 119.13,34.54 119.13,37.34 R27.2
N$32  (via drill 0.3)
  Top 0.305: S1.B2 S1.B1 193.04,7.62 v193.04,15.24 | v85.6,33.27 83.57,35.31 83.57,36.32 83.31,36.58 IC9.9 | v112.01,33.27 111.76,33.02 111.76,28.96 122.94,17.78 185.93,17.78 187.96,15.75 R10.2
  Bottom 0.305: v85.6,33.27 v112.01,33.27 | R10.2 v193.04,15.24
N$33
  Top 0.305: S2.B2 S2.B1 181.61,5.08 175.77,10.92 172.72,10.92 | 172.72,10.92 170.69,8.89 170.69,5.59 100.33,5.59 98.81,7.11 98.81,8.64 87.12,20.32 87.12,29.21 81.03,35.31 81.03,36.32 80.77,36.58 IC9.10 | 172.72,10.92 R25.2
N$34
  Top 0.305: R23.1 224.79,7.62 LED2.K
N$35  (via drill 5)
  other vias: 12.7,34.64
N$40
  Top 0.305: RX.MP 58.42,13.46 65.02,20.07 65.02,21.08 65.28,21.34 IC9.25
N$41
  Top 0.305: TX.MP 63.5,16 67.56,20.07 67.56,21.08 67.82,21.34 IC9.26
N$42  (via drill 0.3)
  Top 0.305: v98.04,11.94 89.66,20.32 89.66,31.75 86.11,35.31 86.11,36.32 85.85,36.58 IC9.8
  Bottom 0.305: v98.04,11.94 157.23,11.94 161.29,7.87 161.8,7.87 162.05,7.62 R24.2
N$47  (via drill 0.3)
  Top 0.305: LED3.A 153.92,35.81 v153.92,43.69
  Bottom 0.305: IC10.16 186.44,59.44 183.64,59.44 180.09,55.88 166.37,55.88 154.18,43.69 v153.92,43.69
N$48  (via drill 0.3)
  Top 0.305: LED4.A 162.05,36.32 166.37,36.32 v166.37,46.74
  Bottom 0.305: 185.67,57.15 IC10.15 185.42,57.15 181.61,53.34 172.97,53.34 v166.37,46.74
N$49  (via drill 0.3)
  Top 0.305: LED5.A 165.1,33.02 171.45,39.37 171.45,48.77 v171.2,49.02
  Bottom 0.305: IC10.14 186.44,54.36 184.15,54.36 180.59,50.8 172.97,50.8 v171.2,49.02
N$50  (via drill 0.3)
  Top 0.305: IC10.13 185.67,52.07 183.9,50.29 183.9,37.85 v184.66,37.08
  Bottom 0.305: LED6.A 178.05,37.08 v184.66,37.08
N$51
  Top 0.305: R30.2 149.61,25.65 149.61,28.45 149.86,28.7 LED3.K
N$52
  Top 0.305: R29.2 157.23,25.65 157.23,28.45 157.48,28.7 LED4.K
N$53
  Top 0.305: R28.2 164.85,25.65 164.85,28.45 165.1,28.7 LED5.K
N$54
  Top 0.305: R26.2 172.47,25.65 172.47,28.45 172.72,28.7 LED6.K
PGC
  Top 0.305: IC9.39 101.09,21.34 101.35,21.08 101.35,10.41 101.09,10.16 101.09,8.89 JP1.5
PGD
  Top 0.305: IC9.40 103.63,21.34 103.89,21.08 103.89,10.41 103.63,10.16 103.63,8.89 JP1.4
PHI1  (via drill 0.3)
  Top 0.305: v96.01,27.94 88.65,35.31 88.65,36.32 88.39,36.58 IC9.7
  Bottom 0.305: v96.01,27.94 98.04,25.91 137.16,25.91 140.72,29.46 140.72,32.77 143.26,32.77 IC6.3
PHI2
  Bottom 0.305: IC6.6 142.49,40.64 141.48,39.62 70.61,39.62 70.61,36.83 IC9.14
RESET
  Bottom 0.305: IC9.28 73.15,21.59 73.15,34.04 128.52,34.04 129.79,35.31 131.32,35.31 131.57,35.56 R5.1 132.33,35.56 134.62,33.27 135.64,33.27 IC6.14
SYNC
  Bottom 0.305: 180.59,21.84 181.86,23.11 181.86,24.13 IC3.2 | 180.59,21.84 180.34,21.59 152.15,21.59 144.78,28.96 140.97,28.96 137.41,25.4 98.55,25.4 98.55,21.59 IC9.38 | R21.1 185.67,21.34 181.1,21.34 180.59,21.84
TEST  (via drill 0.3)
  Top 0.305: v130.05,34.54 130.05,38.35 134.87,43.18 IC6.10
  Bottom 0.305: v130.05,34.54 129.79,34.54 128.78,33.53 114.3,33.53 109.73,28.96 95.5,28.96 92.2,25.65 91.95,25.65 91.95,20.57 90.17,18.8 70.36,18.8 70.36,21.34 IC9.27
VPP
  Top 0.305: JP1.1 111,8.89 110.74,9.14 110.74,10.67 108.97,12.45 108.97,37.34 R27.1
  Bottom 0.305: IC9.1 103.63,36.83 103.89,37.08 108.46,37.08 108.71,37.34 108.97,37.34 R27.1

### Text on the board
tNames: GND | 4004 peripherals emulator and tester, revision B | http://www.frank-buss.de/4004/index.html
